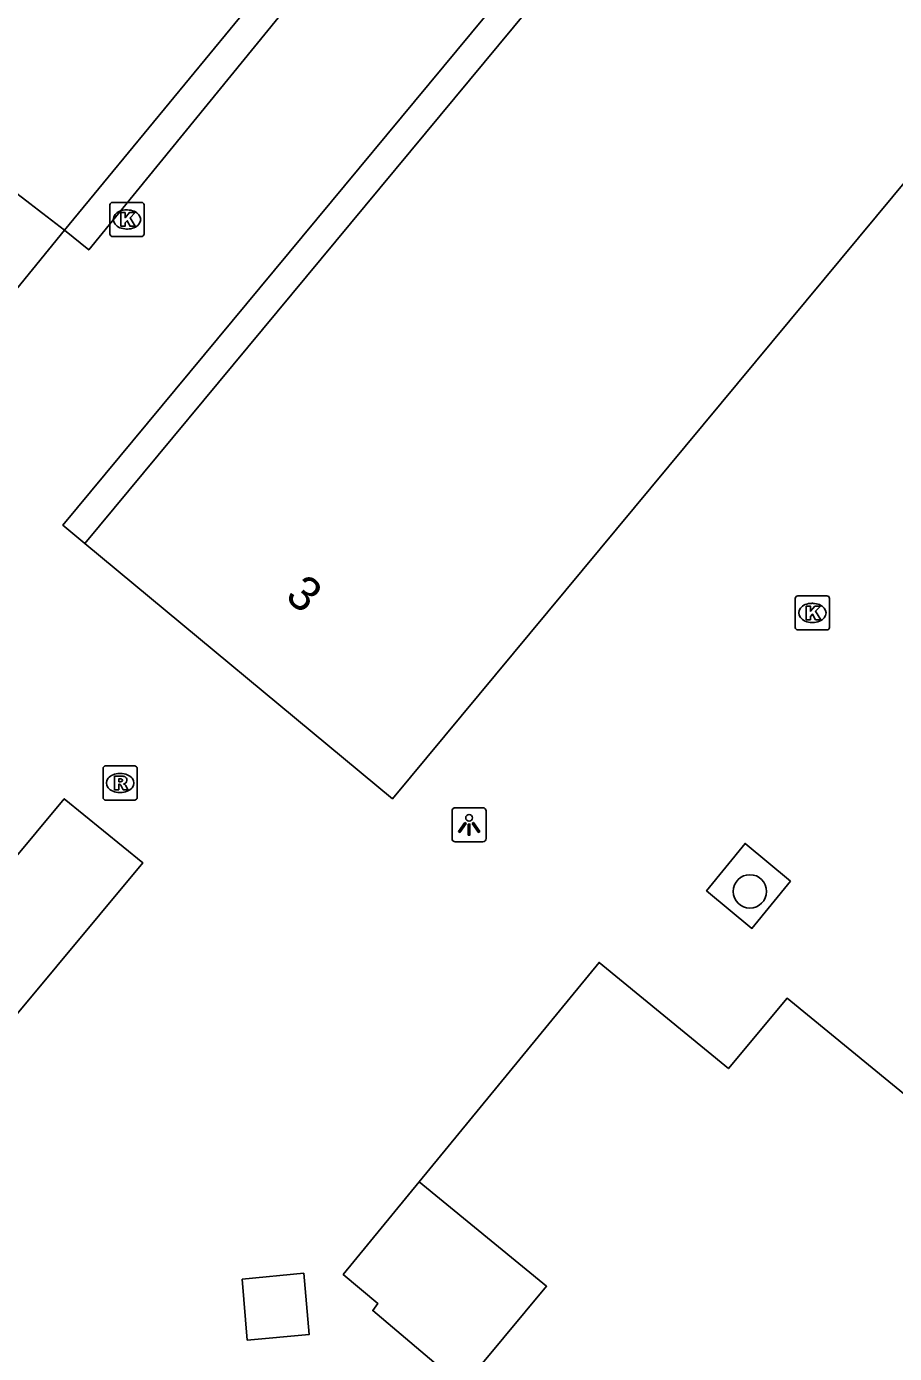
# Model space of a CAD drawing. Extents: x 161772 to 163123, y 383092 to 383917.
# Drawn here: x 161997.61 to 162023.03, y 383273.46 to 383312.33 of the extents above; entities that cross this region are included whole.
import ezdxf

# ---------------------------------------------------------------- set-up
doc = ezdxf.new("R2010")
doc.units = 0
for name, color, linetype in [('IMGEO_Boom', 7, 'Continuous'), ('IMGEO_Kolk', 7, 'Continuous'), ('IMGEO_Lichtpunt', 7, 'Continuous'), ('IMGEO_Pand', 7, 'Continuous'), ('IMGEO_Pand_nummerreeks', 7, 'Continuous'), ('IMGEO_Rijbaan_lokaal_open', 7, 'Continuous'), ('IMGEO_Rioolput', 7, 'Continuous')]:
    doc.layers.add(name, color=color, linetype=linetype)

msp = doc.modelspace()

# ---------------------------------------------------------------- linework, layer by layer
at = {"layer": 'IMGEO_Boom'}
msp.add_circle((162018.794, 383286.997), 0.489, dxfattribs=at)
at = {"layer": 'IMGEO_Kolk'}
for p, q in [((162000.051, 383306.249), (162000.051, 383307.101)), ((162000.126, 383307.175), (162000.978, 383307.175)), ((162000.539, 383306.955), (162000.564, 383306.955)), ((162001.052, 383307.101), (162001.052, 383306.249)), ((162000.978, 383306.175), (162000.126, 383306.175)), ((162000.562, 383306.395), (162000.537, 383306.395)), ((162020.124, 383294.727), (162020.124, 383295.579)), ((162020.199, 383295.653), (162021.051, 383295.653)), ((162021.125, 383295.579), (162021.125, 383294.727)), ((162020.612, 383295.433), (162020.637, 383295.433)), ((162020.635, 383294.873), (162020.61, 383294.873)), ((162021.051, 383294.653), (162020.199, 383294.653))]:
    msp.add_line(p, q, dxfattribs=at)
for points in [[(162000.051, 383306.249), (162000.051, 383307.101)], [(162000.126, 383307.175), (162000.978, 383307.175)], [(162000.372, 383306.875), (162000.495, 383306.875), (162000.495, 383306.724), (162000.625, 383306.875), (162000.789, 383306.875), (162000.643, 383306.724), (162000.796, 383306.475), (162000.644, 383306.475), (162000.559, 383306.639), (162000.495, 383306.572), (162000.495, 383306.475), (162000.372, 383306.475), (162000.372, 383306.875)], [(162001.052, 383307.101), (162001.052, 383306.249)], [(162000.978, 383306.175), (162000.126, 383306.175)], [(162020.124, 383294.727), (162020.124, 383295.579)], [(162020.199, 383295.653), (162021.051, 383295.653)], [(162021.125, 383295.579), (162021.125, 383294.727)], [(162020.445, 383295.353), (162020.568, 383295.353), (162020.568, 383295.202), (162020.698, 383295.353), (162020.862, 383295.353), (162020.716, 383295.202), (162020.869, 383294.953), (162020.717, 383294.953), (162020.632, 383295.117), (162020.568, 383295.05), (162020.568, 383294.953), (162020.445, 383294.953), (162020.445, 383295.353)], [(162021.051, 383294.653), (162020.199, 383294.653)]]:
    msp.add_lwpolyline(points, dxfattribs=at)
for centre, start, end in [((162000.128, 383307.099), 91.552, 178.448), ((162000.128, 383307.099), 91.552, 178.448), ((162000.976, 383307.099), 1.552, 88.448), ((162000.976, 383307.099), 1.552, 88.448), ((162000.128, 383306.251), 181.552, 268.448), ((162000.128, 383306.251), 181.552, 268.448), ((162000.976, 383306.251), 271.552, 358.448), ((162000.976, 383306.251), 271.552, 358.448), ((162020.201, 383295.577), 91.552, 178.448), ((162020.201, 383295.577), 91.552, 178.448), ((162021.049, 383295.577), 1.552, 88.448), ((162021.049, 383295.577), 1.552, 88.448), ((162020.201, 383294.729), 181.552, 268.448), ((162020.201, 383294.729), 181.552, 268.448), ((162021.049, 383294.729), 271.552, 358.448), ((162021.049, 383294.729), 271.552, 358.448)]:
    msp.add_arc(centre, 0.0765, start, end, dxfattribs=at)
for centre, major_axis, ratio, start_param, end_param in [((162000.538, 383306.675), (-0.387, 0.002), 0.722429, 4.712389, 7.853982), ((162000.563, 383306.675), (-0.39, 0.002), 0.717154, 1.570796, 4.712389), ((162020.611, 383295.153), (-0.387, 0.002), 0.722429, 4.712389, 7.853982), ((162020.636, 383295.153), (-0.39, 0.002), 0.717154, 1.570796, 4.712389)]:
    msp.add_ellipse(centre, major_axis=major_axis, ratio=ratio, start_param=start_param, end_param=end_param, dxfattribs=at)
at = {"layer": 'IMGEO_Lichtpunt'}
for p, q in [((162010.072, 383289.352), (162010.072, 383288.545)), ((162010.072, 383289.352), (162010.072, 383288.545)), ((162010.974, 383289.447), (162010.166, 383289.447)), ((162010.974, 383289.447), (162010.166, 383289.447)), ((162011.068, 383288.545), (162011.068, 383289.352)), ((162011.068, 383288.545), (162011.068, 383289.352)), ((162010.166, 383288.451), (162010.974, 383288.451)), ((162010.166, 383288.451), (162010.974, 383288.451))]:
    msp.add_line(p, q, dxfattribs=at)
for points in [[(162010.446, 383289.016), (162010.485, 383288.988), (162010.297, 383288.726), (162010.259, 383288.753), (162010.446, 383289.016)], [(162010.548, 383288.968), (162010.595, 383288.968), (162010.595, 383288.646), (162010.548, 383288.646), (162010.548, 383288.968)], [(162010.658, 383288.988), (162010.696, 383289.015), (162010.883, 383288.753), (162010.844, 383288.725), (162010.658, 383288.988)]]:
    msp.add_lwpolyline(points, dxfattribs=at)
msp.add_circle((162010.571, 383289.15), 0.0994, dxfattribs=at)
for centre, start, end in [((162010.166, 383289.352), 90, 180), ((162010.166, 383289.352), 90, 180), ((162010.974, 383289.352), 0, 90), ((162010.974, 383289.352), 0, 90), ((162010.166, 383288.545), 180, 270), ((162010.166, 383288.545), 180, 270), ((162010.974, 383288.545), 270, 0), ((162010.974, 383288.545), 270, 360)]:
    msp.add_arc(centre, 0.0946, start, end, dxfattribs=at)
at = {"layer": 'IMGEO_Pand'}
for points in [[(161998.722, 383306.358), (162000, 383307.909), (162012.507, 383323.09), (162012.326, 383323.241), (162012.491, 383323.441)], [(162017.506, 383319.099), (162026.521, 383311.615), (162008.327, 383289.709), (161999.317, 383297.187)], [(162017.506, 383319.099), (161999.317, 383297.187)], [(161998.722, 383306.358), (161996.945, 383307.727), (161994.696, 383309.714), (161992.656, 383311.418)], [(162021.258, 383264.714), (162027.134, 383259.881), (162036.134, 383270.654), (162028.327, 383276.946), (162019.883, 383283.867), (162018.165, 383281.809), (162014.379, 383284.914), (162009.111, 383278.492)], [(162009.111, 383278.492), (162012.84, 383275.431), (162010.962, 383273.181), (162016.121, 383268.939)]]:
    msp.add_lwpolyline(points, dxfattribs=at)
at = {"layer": 'IMGEO_Rijbaan_lokaal_open'}
for points in [[(162012.491, 383323.441), (162013.295, 383322.786), (161999.43, 383305.781), (161998.722, 383306.358)], [(161999.317, 383297.187), (161998.671, 383297.723), (162016.845, 383319.622), (162017.506, 383319.099)], [(161994.594, 383304.679), (161996.242, 383303.323), (161998.722, 383306.358)], [(161988.513, 383272.817), (161986.219, 383274.71), (161988.857, 383277.877), (161998.713, 383289.711), (162001.02, 383287.832), (161988.513, 383272.817)], [(162019.985, 383287.296), (162018.856, 383285.911), (162017.527, 383287.015), (162018.656, 383288.4), (162019.985, 383287.296)], [(162016.121, 383268.939), (162015.661, 383268.403), (162010.561, 383272.701), (162010.293, 383272.927), (162010.119, 383272.72), (162007.748, 383274.718), (162007.901, 383274.927), (162006.887, 383275.781), (162009.111, 383278.492)], [(162005.73, 383275.811), (162005.884, 383274.015), (162004.073, 383273.854), (162003.928, 383275.636), (162005.73, 383275.811)]]:
    msp.add_lwpolyline(points, dxfattribs=at)
at = {"layer": 'IMGEO_Rioolput'}
for p, q in [((161999.85, 383289.745), (161999.85, 383290.597)), ((161999.925, 383290.671), (162000.777, 383290.671)), ((162000.851, 383290.597), (162000.851, 383289.745)), ((162000.338, 383290.451), (162000.363, 383290.451)), ((162000.361, 383289.891), (162000.336, 383289.891)), ((162000.777, 383289.671), (161999.925, 383289.671))]:
    msp.add_line(p, q, dxfattribs=at)
for points in [[(161999.85, 383289.745), (161999.85, 383290.597)], [(161999.925, 383290.671), (162000.777, 383290.671)], [(162000.851, 383290.597), (162000.851, 383289.745)], [(162000.439, 383290.369), (162000.187, 383290.371), (162000.187, 383289.971)], [(162000.187, 383289.971), (162000.311, 383289.971), (162000.311, 383290.133), (162000.322, 383290.133)], [(162000.365, 383290.29), (162000.311, 383290.29), (162000.311, 383290.209)], [(162000.311, 383290.209), (162000.363, 383290.209)], [(162000.369, 383290.104), (162000.44, 383289.971), (162000.58, 383289.971), (162000.515, 383290.097)], [(162000.777, 383289.671), (161999.925, 383289.671)]]:
    msp.add_lwpolyline(points, dxfattribs=at)
for centre, radius, start, end in [((161999.927, 383290.595), 0.0765, 91.552, 178.448), ((161999.927, 383290.595), 0.0765, 91.552, 178.448), ((162000.775, 383290.595), 0.0765, 1.552, 88.448), ((162000.775, 383290.595), 0.0765, 1.552, 88.448), ((162000.321, 383290.08), 0.0533, 26.0293, 88.6989), ((162000.347, 383290.398), 0.19, 274.7715, 282.9687), ((162000.371, 383290.194), 0.0964, 77.0061, 93.1865), ((162000.385, 383290.251), 0.0378, 276.6634, 79.6772), ((162000.438, 383290.259), 0.109, 350.3612, 89.416), ((162000.436, 383290.259), 0.112, 277.5842, 350.9817), ((162000.42, 383290.044), 0.108, 29.5134, 73.7905), ((161999.927, 383289.747), 0.0765, 181.552, 268.448), ((161999.927, 383289.747), 0.0765, 181.552, 268.448), ((162000.775, 383289.747), 0.0765, 271.552, 358.448), ((162000.775, 383289.747), 0.0765, 271.552, 358.448)]:
    msp.add_arc(centre, radius, start, end, dxfattribs=at)
for centre, major_axis, ratio, start_param, end_param in [((162000.337, 383290.171), (-0.387, 0.002), 0.722429, 4.712389, 7.853982), ((162000.362, 383290.171), (-0.39, 0.002), 0.717154, 1.570796, 4.712389)]:
    msp.add_ellipse(centre, major_axis=major_axis, ratio=ratio, start_param=start_param, end_param=end_param, dxfattribs=at)

# ---------------------------------------------------------------- texts
at = {"layer": 'IMGEO_Pand_nummerreeks'}
msp.add_text('3', height=1, rotation=320.3112, dxfattribs=at).set_placement((162005.148, 383295.576))

doc.saveas('drawing.dxf')
